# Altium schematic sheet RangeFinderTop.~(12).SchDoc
size A; DocumentNumber: 1; SheetNumber: 1; SheetTotal: 6
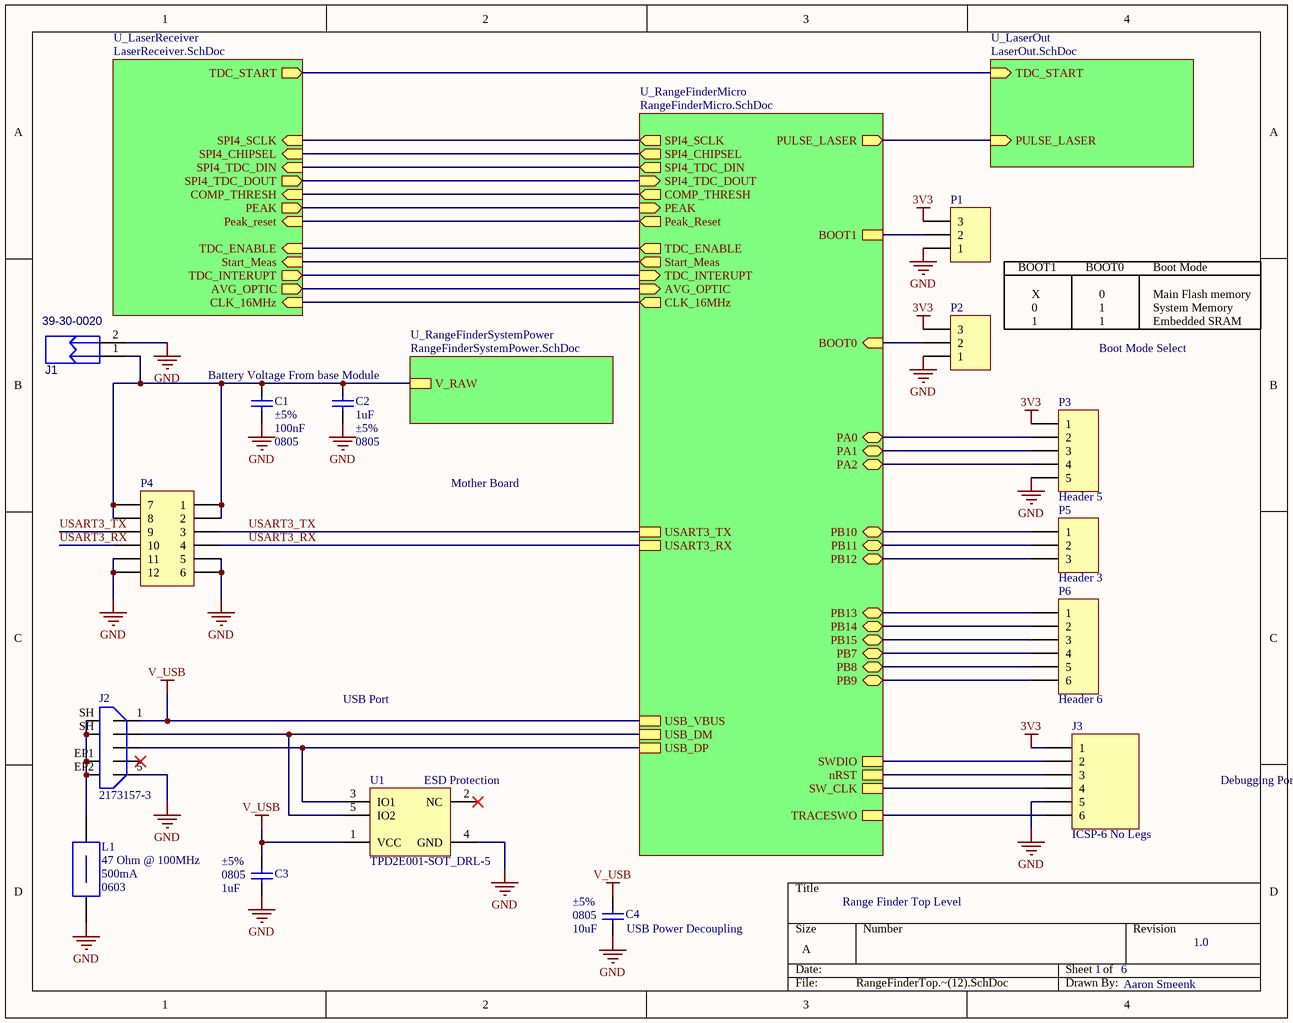
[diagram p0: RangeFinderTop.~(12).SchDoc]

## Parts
C1  value 100nF  Tolerance: ±5%  Case-EIA: 0805  [CAPC0805(2012)100_L]  (hidden comment: CAP 100nF 6.3V 0805(2012))
C2  value 1uF  Tolerance: ±5%  Case-EIA: 0805  [CAPC0805(2012)100_M]  (hidden comment: CAP 1uF 6.3V 0805(2012))
C3  value 1uF  Tolerance: ±5%  Case-EIA: 0805  [CAPC0805(2012)100_M]  (hidden comment: CAP 1uF 6.3V 0805(2012))
C4  value 10uF  Tolerance: ±5%  Case-EIA: 0805  [CAPC0805(2012)100_M]  (hidden comment: CAP 10uF 6.3V 0805(2012))
J1  39-30-0020  [39-30-0020]
J2  2173157-3  [2173157-3]
J3  ICSP-6 No Legs  [TC2030-IDC-NL]
L1  Impedance @ Frequency: 47 Ohm @ 100MHz  Current Rating: 500mA  Package / Case: 0603  [LI0603E470R-10]  (hidden comment: LI0603E470R-10)
P1  Header 3  [HDR1X3]  (value not drawn)
P2  Header 3  [HDR1X3]  (value not drawn)
P3  Header 5  [HDR1X5]
P4  Header 6X2A  [HDR2X6_CEN]  (value not drawn)
P5  Header 3  [HDR1X3]
P6  Header 6  [HDR1X6]
U1  TPD2E001-SOT_DRL-5  [TPD2E001DRLR]

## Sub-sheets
U_LaserOut = LaserOut.SchDoc: PULSE_LASER (in), TDC_START (in)
U_LaserReceiver = LaserReceiver.SchDoc: Start_Meas (in), TDC_ENABLE (in), SPI4_SCLK (in), SPI4_CHIPSEL (in), SPI4_TDC_DIN (in), SPI4_TDC_DOUT (out), TDC_INTERUPT (out), AVG_OPTIC (out), CLK_16MHz (in), TDC_START (out), COMP_THRESH (in), PEAK (out), Peak_reset (in)
U_RangeFinderMicro = RangeFinderMicro.SchDoc: USART3_TX, USART3_RX, SWDIO, SW_CLK, TRACESWO, BOOT1, BOOT0 (in), USB_DP, USB_DM, USB_VBUS, nRST, SPI4_SCLK (out), SPI4_TDC_DOUT (in), SPI4_CHIPSEL (out), SPI4_TDC_DIN (out), Start_Meas (out), TDC_ENABLE (out), TDC_INTERUPT (in), AVG_OPTIC (in), PULSE_LASER (out), CLK_16MHz (out), COMP_THRESH (out), PEAK (in), Peak_Reset (out), PA0 (bidir), PB10 (bidir), PB13 (bidir), PB11 (bidir), PB8 (bidir), PA2 (bidir), PA1 (bidir), PB12 (bidir), PB15 (bidir), PB7 (bidir), PB9 (bidir), PB14 (bidir)
U_RangeFinderSystemPower = RangeFinderSystemPower.SchDoc: V_RAW

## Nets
3V3: J3.1 P1.3 P2.3 P3.1
GND: C1.1 C2.1 C3.1 C4.1 J1.2 J2.5(GND) J3.5 L1.1 P1.1 P2.1 P3.5 P4.5 P4.6 P4.11 P4.12 U1.4(GND)
V_USB: C3.2 C4.2 J2.1(5V) U1.1(VCC) ; sheet U_RangeFinderMicro/USB_VBUS
USART3_RX: P4.4 P4.10 ; sheet U_RangeFinderMicro/USART3_RX
USART3_TX: P4.3 P4.9 ; sheet U_RangeFinderMicro/USART3_TX
NetC1_2: C1.2 C2.2 J1.1 P4.1 P4.2 P4.7 P4.8 ; sheet U_RangeFinderSystemPower/V_RAW
NetJ2_2: J2.2(D-) U1.5(IO2) ; sheet U_RangeFinderMicro/USB_DM
NetJ2_3: J2.3(D+) U1.3(IO1) ; sheet U_RangeFinderMicro/USB_DP
NetJ2_EP1: J2.EP1 J2.EP2 J2.SH L1.2
NetJ3_2: J3.2 ; sheet U_RangeFinderMicro/SWDIO
NetJ3_3: J3.3 ; sheet U_RangeFinderMicro/nRST
NetJ3_4: J3.4 ; sheet U_RangeFinderMicro/SW_CLK
NetJ3_6: J3.6 ; sheet U_RangeFinderMicro/TRACESWO
NetP1_2: P1.2 ; sheet U_RangeFinderMicro/BOOT1
NetP2_2: P2.2 ; sheet U_RangeFinderMicro/BOOT0
NetP3_2: P3.2 ; sheet U_RangeFinderMicro/PA0
NetP3_3: P3.3 ; sheet U_RangeFinderMicro/PA1
NetP3_4: P3.4 ; sheet U_RangeFinderMicro/PA2
NetP5_1: P5.1 ; sheet U_RangeFinderMicro/PB10
NetP5_2: P5.2 ; sheet U_RangeFinderMicro/PB11
NetP5_3: P5.3 ; sheet U_RangeFinderMicro/PB12
NetP6_1: P6.1 ; sheet U_RangeFinderMicro/PB13
NetP6_2: P6.2 ; sheet U_RangeFinderMicro/PB14
NetP6_3: P6.3 ; sheet U_RangeFinderMicro/PB15
NetP6_4: P6.4 ; sheet U_RangeFinderMicro/PB7
NetP6_5: P6.5 ; sheet U_RangeFinderMicro/PB8
NetP6_6: P6.6 ; sheet U_RangeFinderMicro/PB9
(unnamed): sheet U_LaserOut/PULSE_LASER, sheet U_RangeFinderMicro/PULSE_LASER
(unnamed): sheet U_LaserOut/TDC_START, sheet U_LaserReceiver/TDC_START  [a separate net that carries the same name]
(unnamed): sheet U_LaserReceiver/Start_Meas, sheet U_RangeFinderMicro/Start_Meas  [a separate net that carries the same name]
(unnamed): sheet U_LaserReceiver/TDC_ENABLE, sheet U_RangeFinderMicro/TDC_ENABLE  [a separate net that carries the same name]
(unnamed): sheet U_LaserReceiver/SPI4_SCLK, sheet U_RangeFinderMicro/SPI4_SCLK  [a separate net that carries the same name]
(unnamed): sheet U_LaserReceiver/SPI4_CHIPSEL, sheet U_RangeFinderMicro/SPI4_CHIPSEL  [a separate net that carries the same name]
(unnamed): sheet U_LaserReceiver/SPI4_TDC_DIN, sheet U_RangeFinderMicro/SPI4_TDC_DIN  [a separate net that carries the same name]
(unnamed): sheet U_LaserReceiver/SPI4_TDC_DOUT, sheet U_RangeFinderMicro/SPI4_TDC_DOUT  [a separate net that carries the same name]
(unnamed): sheet U_LaserReceiver/TDC_INTERUPT, sheet U_RangeFinderMicro/TDC_INTERUPT  [a separate net that carries the same name]
(unnamed): sheet U_LaserReceiver/AVG_OPTIC, sheet U_RangeFinderMicro/AVG_OPTIC  [a separate net that carries the same name]
(unnamed): sheet U_LaserReceiver/CLK_16MHz, sheet U_RangeFinderMicro/CLK_16MHz  [a separate net that carries the same name]
(unnamed): sheet U_LaserReceiver/COMP_THRESH, sheet U_RangeFinderMicro/COMP_THRESH  [a separate net that carries the same name]
(unnamed): sheet U_LaserReceiver/PEAK, sheet U_RangeFinderMicro/PEAK  [a separate net that carries the same name]
(unnamed): sheet U_LaserReceiver/Peak_reset, sheet U_RangeFinderMicro/Peak_Reset  [a separate net that carries the same name]

Not connected (* = marked no-connect by the designer): J2 4(ID)*; U1 2(NC)*

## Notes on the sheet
- BOOT1
- X
- BOOT0
- 0
- Boot Mode
- Main Flash memory
- 1
- Boot Mode Select
- System Memory
- Embedded SRAM
- Battery Voltage From base Module
- Mother Board
- USB Port
- (near U1) ESD Protection
- Debugging Port
- Range Finder Top Level
- (near C4) USB Power Decoupling
- 6
- 1.0
- Aaron Smeenk

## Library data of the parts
C1 = CMP-1036-04390-1: CAP 100nF 6.3V ±5% 0805 (2012 Metric) Thickness 1mm SMD; Case-Metric: 2012
C2 C3 = CMP-1036-04730-1: CAP 1uF 6.3V ±5% 0805 (2012 Metric) Thickness 1mm SMD; Case-Metric: 2012
C4 = CMP-1036-04730-1: CAP 10uF 6.3V ±5% 0805 (2012 Metric) Thickness 1mm SMD; Case-Metric: 2012
J1 = CMP-00007-A.1: CONN HEADER 2POS 4.2MM R/A TIN
J2 = 2173157-3: USB Connectors SPLASH PROOF MICRO 5P USB B-TYPE; Number of Ports: 1; Number of Contacts: 5; Gender: Female; Brand: TE Connectivity; Mounting Angle: Right
J3 = ICSP-6 No Legs: 6 Pin Connector
L1 = LI0603E470R-10: FERRITE CHIP 47 OHMS 500MA 0603; DC Resistance (DCR): 100 mOhm Max; Filter Type: Differential Mode - Single
P1 P2 P5 = Header 3: Header, 3-Pin
P3 = Header 5: Header, 5-Pin
P4 = Header 6X2A: Header, 6-Pin, Dual row
P6 = Header 6: Header, 6-Pin
U1 = TPD2E001DRLR: TVS DIODE 5.5VWM 100VC SOT5; Bidirectional Channels: 2; Voltage - Reverse Standoff (Typ): 5.5V (Max); Voltage - Breakdown (Min): 11V; Voltage - Clamping (Max) @ Ipp: 100V; Power Line Protection: Yes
